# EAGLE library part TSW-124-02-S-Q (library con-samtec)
THROUGH-HOLE .025" SQ POST HEADER Source: Samtec TSW.pdf
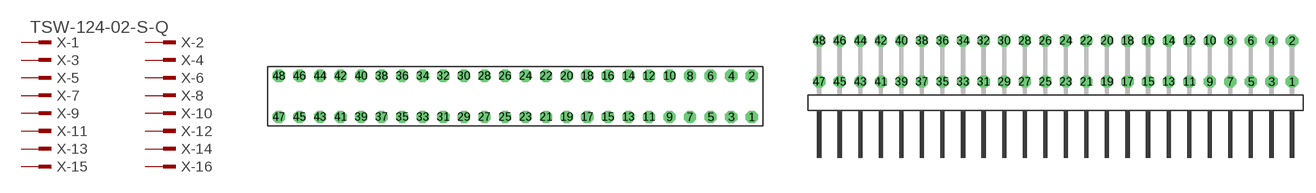
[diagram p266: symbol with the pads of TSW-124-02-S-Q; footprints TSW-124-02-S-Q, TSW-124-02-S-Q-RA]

Designator prefix X; gates -1=MPINV -2=MPIN -3=MPIN -4=MPIN -5=MPIN -6=MPIN -7=MPIN -8=MPIN -9=MPIN -10=MPIN -11=MPIN -12=MPIN -13=MPIN -14=MPIN -15=MPIN -16=MPIN -17=MPIN -18=MPIN -19=MPIN -20=MPIN -21=MPIN -22=MPIN -23=MPIN -24=MPIN -25=MPIN -26=MPIN -27=MPIN -28=MPIN -29=MPIN -30=MPIN -31=MPIN -32=MPIN -33=MPIN -34=MPIN -35=MPIN -36=MPIN -37=MPIN -38=MPIN -39=MPIN -40=MPIN -41=MPIN -42=MPIN -43=MPIN -44=MPIN -45=MPIN -46=MPIN -47=MPIN -48=MPIN

## TSW-124-02-S-Q (OC_FARNELL: unknown; OC_NEWARK: unknown)  [TSW-124-02-S-Q]
1  -1:1  pas
2  -2:1  pas
3  -3:1  pas
4  -4:1  pas
5  -5:1  pas
6  -6:1  pas
7  -7:1  pas
8  -8:1  pas
9  -9:1  pas
10  -10:1  pas
11  -11:1  pas
12  -12:1  pas
13  -13:1  pas
14  -14:1  pas
15  -15:1  pas
16  -16:1  pas
17  -17:1  pas
18  -18:1  pas
19  -19:1  pas
20  -20:1  pas
21  -21:1  pas
22  -22:1  pas
23  -23:1  pas
24  -24:1  pas
25  -25:1  pas
26  -26:1  pas
27  -27:1  pas
28  -28:1  pas
29  -29:1  pas
30  -30:1  pas
31  -31:1  pas
32  -32:1  pas
33  -33:1  pas
34  -34:1  pas
35  -35:1  pas
36  -36:1  pas
37  -37:1  pas
38  -38:1  pas
39  -39:1  pas
40  -40:1  pas
41  -41:1  pas
42  -42:1  pas
43  -43:1  pas
44  -44:1  pas
45  -45:1  pas
46  -46:1  pas
47  -47:1  pas
48  -48:1  pas

## TSW-124-02-S-Q-RA (OC_FARNELL: unknown; OC_NEWARK: unknown)  [TSW-124-02-S-Q-RA]
Pads as for TSW-124-02-S-Q

## Footprint TSW-124-02-S-Q (pad centres in mm)
THROUGH-HOLE .025" SQ POST HEADER Source: Samtec TSW.pdf
drill 1 pad 1.5 octagon: 1 29.21,-2.54; 2 29.21,2.54; 3 26.67,-2.54; 4 26.67,2.54; 5 24.13,-2.54; 6 24.13,2.54; 7 21.59,-2.54; 8 21.59,2.54; 9 19.05,-2.54; 10 19.05,2.54; 11 16.51,-2.54; 12 16.51,2.54; 13 13.97,-2.54; 14 13.97,2.54; 15 11.43,-2.54; 16 11.43,2.54; 17 8.89,-2.54; 18 8.89,2.54; 19 6.35,-2.54; 20 6.35,2.54; 21 3.81,-2.54; 22 3.81,2.54; 23 1.27,-2.54; 24 1.27,2.54; 25 -1.27,-2.54; 26 -1.27,2.54; 27 -3.81,-2.54; 28 -3.81,2.54; 29 -6.35,-2.54; 30 -6.35,2.54; 31 -8.89,-2.54; 32 -8.89,2.54; 33 -11.43,-2.54; 34 -11.43,2.54; 35 -13.97,-2.54; 36 -13.97,2.54; 37 -16.51,-2.54; 38 -16.51,2.54; 39 -19.05,-2.54; 40 -19.05,2.54; 41 -21.59,-2.54; 42 -21.59,2.54; 43 -24.13,-2.54; 44 -24.13,2.54; 45 -26.67,-2.54; 46 -26.67,2.54; 47 -29.21,-2.54; 48 -29.21,2.54

## Footprint TSW-124-02-S-Q-RA (pad centres in mm)
THROUGH-HOLE .025" SQ POST HEADER Source: Samtec TSW.pdf
drill 1 pad 1.5 octagon: 1 29.21,1.524; 2 29.21,6.604; 3 26.67,1.524; 4 26.67,6.604; 5 24.13,1.524; 6 24.13,6.604; 7 21.59,1.524; 8 21.59,6.604; 9 19.05,1.524; 10 19.05,6.604; 11 16.51,1.524; 12 16.51,6.604; 13 13.97,1.524; 14 13.97,6.604; 15 11.43,1.524; 16 11.43,6.604; 17 8.89,1.524; 18 8.89,6.604; 19 6.35,1.524; 20 6.35,6.604; 21 3.81,1.524; 22 3.81,6.604; 23 1.27,1.524; 24 1.27,6.604; 25 -1.27,1.524; 26 -1.27,6.604; 27 -3.81,1.524; 28 -3.81,6.604; 29 -6.35,1.524; 30 -6.35,6.604; 31 -8.89,1.524; 32 -8.89,6.604; 33 -11.43,1.524; 34 -11.43,6.604; 35 -13.97,1.524; 36 -13.97,6.604; 37 -16.51,1.524; 38 -16.51,6.604; 39 -19.05,1.524; 40 -19.05,6.604; 41 -21.59,1.524; 42 -21.59,6.604; 43 -24.13,1.524; 44 -24.13,6.604; 45 -26.67,1.524; 46 -26.67,6.604; 47 -29.21,1.524; 48 -29.21,6.604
